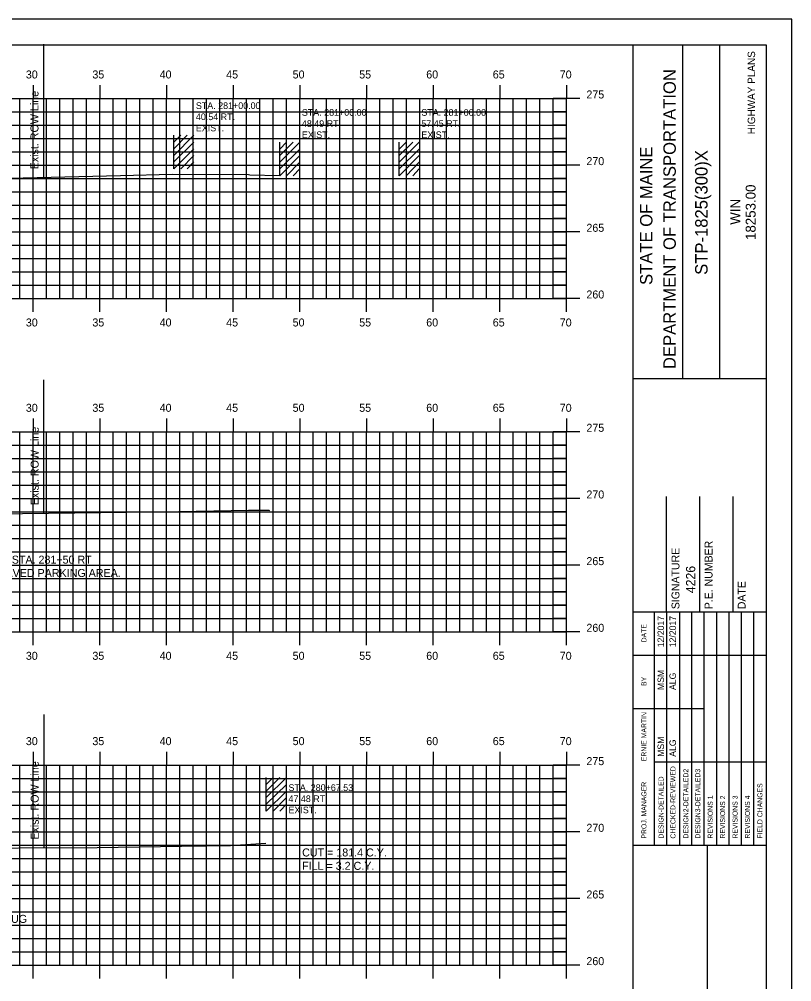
# Model space of a CAD drawing. Extents: x 855344 to 855514, y 366268 to 366378.
# Drawn here: x 855456.1 to 855514, y 366306 to 366378.2 of the extents above; entities that cross this region are included whole.
import ezdxf

# ---------------------------------------------------------------- set-up
doc = ezdxf.new("R2010")
doc.units = 0
for name, color, linetype in [('ANNOTATION', 7, 'Continuous'), ('BORDER', 7, 'Continuous'), ('D_Text_Monospaced', 7, 'Continuous'), ('E_ROW_Line', 7, 'Continuous'), ('H_V ANNOTATION', 7, 'Continuous'), ('HIGHWAY_TITLE', 7, 'Continuous'), ('MAJOR', 7, 'Continuous'), ('MINOR', 7, 'Continuous'), ('PLOT BOUNDARY', 7, 'Continuous'), ('S_Buildings', 7, 'Continuous'), ('S_Buildings_Attachments', 7, 'Continuous'), ('S_Buildings_SillElevation', 7, 'Continuous'), ('S_Roadway_Centerline', 7, 'Continuous')]:
    doc.layers.add(name, color=color, linetype=linetype)

msp = doc.modelspace()

# ---------------------------------------------------------------- linework, layer by layer
at = {"layer": 'BORDER'}
for p, q in [((855512.11, 366376.236), (855352.11, 366376.236)), ((855502.11, 366271.236), (855502.11, 366376.239)), ((855505.838, 366351.234), (855505.838, 366376.234)), ((855508.633, 366351.234), (855508.633, 366376.234)), ((855512.11, 366271.236), (855512.11, 366376.236)), ((855502.111, 366351.231), (855512.11, 366351.231)), ((855504.61, 366333.739), (855504.61, 366342.387)), ((855507.11, 366333.739), (855507.11, 366342.387)), ((855509.61, 366333.739), (855509.61, 366342.387)), ((855502.11, 366333.739), (855512.11, 366333.739)), ((855502.11, 366316.239), (855512.11, 366316.239)), ((855507.701, 366281.239), (855507.701, 366316.239))]:
    msp.add_line(p, q, dxfattribs=at)
for points in [[(855503.725, 366330.489), (855503.725, 366333.739)], [(855504.657, 366316.242), (855504.657, 366333.739)], [(855505.589, 366333.739), (855505.589, 366316.242)], [(855506.521, 366316.242), (855506.521, 366333.739)], [(855507.452, 366316.242), (855507.452, 366333.739)], [(855508.384, 366316.242), (855508.384, 366333.739)], [(855509.316, 366316.242), (855509.316, 366333.739)], [(855510.247, 366316.242), (855510.247, 366333.739)], [(855511.179, 366316.242), (855511.179, 366333.739)], [(855503.726, 366316.242), (855503.726, 366333.033)], [(855502.11, 366330.489), (855512.11, 366330.489)], [(855502.11, 366326.489), (855503.726, 366326.489)], [(855503.725, 366326.489), (855507.451, 366326.489)], [(855503.725, 366322.489), (855512.11, 366322.489)]]:
    msp.add_lwpolyline(points, dxfattribs=at)
at = {"layer": 'E_ROW_Line'}
for p, q in [((855457.905, 366366.321), (855457.905, 366376.321)), ((855457.92, 366341.126), (855457.92, 366351.126)), ((855457.925, 366316.044), (855457.925, 366326.044))]:
    msp.add_line(p, q, dxfattribs=at)
at = {"layer": 'MAJOR'}
for p, q in [((855457.11, 366373.238), (855457.11, 366372.236)), ((855462.11, 366373.238), (855462.11, 366372.236)), ((855467.11, 366373.238), (855467.11, 366372.236)), ((855472.11, 366373.238), (855472.11, 366372.236)), ((855477.11, 366373.238), (855477.11, 366372.236)), ((855482.11, 366373.238), (855482.11, 366372.236)), ((855487.11, 366373.238), (855487.11, 366372.236)), ((855492.11, 366373.238), (855492.11, 366372.236)), ((855497.11, 366373.238), (855497.11, 366372.236)), ((855357.11, 366372.236), (855497.11, 366372.236)), ((855357.11, 366372.236), (855497.11, 366372.236)), ((855457.11, 366357.236), (855457.11, 366372.236)), ((855462.11, 366357.236), (855462.11, 366372.236)), ((855467.11, 366357.236), (855467.11, 366372.236)), ((855472.11, 366357.236), (855472.11, 366372.236)), ((855477.11, 366357.236), (855477.11, 366372.236)), ((855482.11, 366357.236), (855482.11, 366372.236)), ((855487.11, 366357.236), (855487.11, 366372.236)), ((855492.11, 366357.236), (855492.11, 366372.236)), ((855498.112, 366372.236), (855496.108, 366372.236)), ((855497.11, 366357.236), (855497.11, 366372.236)), ((855497.11, 366357.236), (855497.11, 366372.236)), ((855357.11, 366367.236), (855497.11, 366367.236)), ((855498.112, 366367.236), (855496.108, 366367.236)), ((855357.11, 366362.236), (855497.11, 366362.236)), ((855498.112, 366362.236), (855496.108, 366362.236)), ((855357.11, 366357.236), (855497.11, 366357.236)), ((855357.11, 366357.236), (855497.11, 366357.236)), ((855457.11, 366356.234), (855457.11, 366357.236)), ((855462.11, 366356.234), (855462.11, 366357.236)), ((855467.11, 366356.234), (855467.11, 366357.236)), ((855472.11, 366356.234), (855472.11, 366357.236)), ((855477.11, 366356.234), (855477.11, 366357.236)), ((855482.11, 366356.234), (855482.11, 366357.236)), ((855487.11, 366356.234), (855487.11, 366357.236)), ((855492.11, 366356.234), (855492.11, 366357.236)), ((855498.112, 366357.236), (855496.108, 366357.236)), ((855497.11, 366356.234), (855497.11, 366357.236)), ((855457.11, 366348.238), (855457.11, 366347.236)), ((855462.11, 366348.238), (855462.11, 366347.236)), ((855467.11, 366348.238), (855467.11, 366347.236)), ((855472.11, 366348.238), (855472.11, 366347.236)), ((855477.11, 366348.238), (855477.11, 366347.236)), ((855482.11, 366348.238), (855482.11, 366347.236)), ((855487.11, 366348.238), (855487.11, 366347.236)), ((855492.11, 366348.238), (855492.11, 366347.236)), ((855497.11, 366348.238), (855497.11, 366347.236)), ((855357.11, 366347.236), (855497.11, 366347.236)), ((855357.11, 366347.236), (855497.11, 366347.236)), ((855457.11, 366332.236), (855457.11, 366347.236)), ((855462.11, 366332.236), (855462.11, 366347.236)), ((855467.11, 366332.236), (855467.11, 366347.236)), ((855472.11, 366332.236), (855472.11, 366347.236)), ((855477.11, 366332.236), (855477.11, 366347.236)), ((855482.11, 366332.236), (855482.11, 366347.236)), ((855487.11, 366332.236), (855487.11, 366347.236)), ((855492.11, 366332.236), (855492.11, 366347.236)), ((855498.112, 366347.236), (855496.108, 366347.236)), ((855497.11, 366332.236), (855497.11, 366347.236)), ((855497.11, 366332.236), (855497.11, 366347.236)), ((855357.11, 366342.236), (855497.11, 366342.236)), ((855498.112, 366342.236), (855496.108, 366342.236)), ((855357.11, 366337.236), (855497.11, 366337.236)), ((855498.112, 366337.236), (855496.108, 366337.236)), ((855357.11, 366332.236), (855497.11, 366332.236)), ((855357.11, 366332.236), (855497.11, 366332.236)), ((855457.11, 366331.234), (855457.11, 366332.236)), ((855462.11, 366331.234), (855462.11, 366332.236)), ((855467.11, 366331.234), (855467.11, 366332.236)), ((855472.11, 366331.234), (855472.11, 366332.236)), ((855477.11, 366331.234), (855477.11, 366332.236)), ((855482.11, 366331.234), (855482.11, 366332.236)), ((855487.11, 366331.234), (855487.11, 366332.236)), ((855492.11, 366331.234), (855492.11, 366332.236)), ((855498.112, 366332.236), (855496.108, 366332.236)), ((855497.11, 366331.234), (855497.11, 366332.236)), ((855457.11, 366323.238), (855457.11, 366322.236)), ((855462.11, 366323.238), (855462.11, 366322.236)), ((855467.11, 366323.238), (855467.11, 366322.236)), ((855472.11, 366323.238), (855472.11, 366322.236)), ((855477.11, 366323.238), (855477.11, 366322.236)), ((855482.11, 366323.238), (855482.11, 366322.236)), ((855487.11, 366323.238), (855487.11, 366322.236)), ((855492.11, 366323.238), (855492.11, 366322.236)), ((855497.11, 366323.238), (855497.11, 366322.236)), ((855357.11, 366322.236), (855497.11, 366322.236)), ((855357.11, 366322.236), (855497.11, 366322.236)), ((855457.11, 366307.236), (855457.11, 366322.236)), ((855462.11, 366307.236), (855462.11, 366322.236)), ((855467.11, 366307.236), (855467.11, 366322.236)), ((855472.11, 366307.236), (855472.11, 366322.236)), ((855477.11, 366307.236), (855477.11, 366322.236)), ((855482.11, 366307.236), (855482.11, 366322.236)), ((855487.11, 366307.236), (855487.11, 366322.236)), ((855492.11, 366307.236), (855492.11, 366322.236)), ((855498.112, 366322.236), (855496.108, 366322.236)), ((855497.11, 366307.236), (855497.11, 366322.236)), ((855497.11, 366307.236), (855497.11, 366322.236)), ((855357.11, 366317.236), (855497.11, 366317.236)), ((855498.112, 366317.236), (855496.108, 366317.236)), ((855357.11, 366312.236), (855497.11, 366312.236)), ((855498.112, 366312.236), (855496.108, 366312.236)), ((855357.11, 366307.236), (855497.11, 366307.236)), ((855357.11, 366307.236), (855497.11, 366307.236)), ((855457.11, 366306.234), (855457.11, 366307.236)), ((855462.11, 366306.234), (855462.11, 366307.236)), ((855467.11, 366306.234), (855467.11, 366307.236)), ((855472.11, 366306.234), (855472.11, 366307.236)), ((855477.11, 366306.234), (855477.11, 366307.236)), ((855482.11, 366306.234), (855482.11, 366307.236)), ((855487.11, 366306.234), (855487.11, 366307.236)), ((855492.11, 366306.234), (855492.11, 366307.236)), ((855498.112, 366307.236), (855496.108, 366307.236)), ((855497.11, 366306.234), (855497.11, 366307.236))]:
    msp.add_line(p, q, dxfattribs=at)
at = {"layer": 'MINOR'}
for p, q in [((855456.11, 366357.236), (855456.11, 366372.236)), ((855458.11, 366357.236), (855458.11, 366372.236)), ((855459.11, 366357.236), (855459.11, 366372.236)), ((855460.11, 366357.236), (855460.11, 366372.236)), ((855461.11, 366357.236), (855461.11, 366372.236)), ((855463.11, 366357.236), (855463.11, 366372.236)), ((855464.11, 366357.236), (855464.11, 366372.236)), ((855465.11, 366357.236), (855465.11, 366372.236)), ((855466.11, 366357.236), (855466.11, 366372.236)), ((855468.11, 366357.236), (855468.11, 366372.236)), ((855469.11, 366357.236), (855469.11, 366372.236)), ((855470.11, 366357.236), (855470.11, 366372.236)), ((855471.11, 366357.236), (855471.11, 366372.236)), ((855473.11, 366357.236), (855473.11, 366372.236)), ((855474.11, 366357.236), (855474.11, 366372.236)), ((855475.11, 366357.236), (855475.11, 366372.236)), ((855476.11, 366357.236), (855476.11, 366372.236)), ((855478.11, 366357.236), (855478.11, 366372.236)), ((855479.11, 366357.236), (855479.11, 366372.236)), ((855480.11, 366357.236), (855480.11, 366372.236)), ((855481.11, 366357.236), (855481.11, 366372.236)), ((855483.11, 366357.236), (855483.11, 366372.236)), ((855484.11, 366357.236), (855484.11, 366372.236)), ((855485.11, 366357.236), (855485.11, 366372.236)), ((855486.11, 366357.236), (855486.11, 366372.236)), ((855488.11, 366357.236), (855488.11, 366372.236)), ((855489.11, 366357.236), (855489.11, 366372.236)), ((855490.11, 366357.236), (855490.11, 366372.236)), ((855491.11, 366357.236), (855491.11, 366372.236)), ((855493.11, 366357.236), (855493.11, 366372.236)), ((855494.11, 366357.236), (855494.11, 366372.236)), ((855495.11, 366357.236), (855495.11, 366372.236)), ((855496.11, 366357.236), (855496.11, 366372.236)), ((855357.11, 366371.236), (855497.11, 366371.236)), ((855497.11, 366371.236), (855496.108, 366371.236)), ((855357.11, 366370.236), (855497.11, 366370.236)), ((855497.11, 366370.236), (855496.108, 366370.236)), ((855357.11, 366369.236), (855497.11, 366369.236)), ((855497.11, 366369.236), (855496.108, 366369.236)), ((855357.11, 366368.236), (855497.11, 366368.236)), ((855497.11, 366368.236), (855496.108, 366368.236)), ((855357.11, 366366.236), (855497.11, 366366.236)), ((855497.11, 366366.236), (855496.108, 366366.236)), ((855357.11, 366365.236), (855497.11, 366365.236)), ((855497.11, 366365.236), (855496.108, 366365.236)), ((855357.11, 366364.236), (855497.11, 366364.236)), ((855497.11, 366364.236), (855496.108, 366364.236)), ((855357.11, 366363.236), (855497.11, 366363.236)), ((855497.11, 366363.236), (855496.108, 366363.236)), ((855357.11, 366361.236), (855497.11, 366361.236)), ((855497.11, 366361.236), (855496.108, 366361.236)), ((855357.11, 366360.236), (855497.11, 366360.236)), ((855497.11, 366360.236), (855496.108, 366360.236)), ((855357.11, 366359.236), (855497.11, 366359.236)), ((855497.11, 366359.236), (855496.108, 366359.236)), ((855357.11, 366358.236), (855497.11, 366358.236)), ((855497.11, 366358.236), (855496.108, 366358.236)), ((855456.11, 366332.236), (855456.11, 366347.236)), ((855458.11, 366332.236), (855458.11, 366347.236)), ((855459.11, 366332.236), (855459.11, 366347.236)), ((855460.11, 366332.236), (855460.11, 366347.236)), ((855461.11, 366332.236), (855461.11, 366347.236)), ((855463.11, 366332.236), (855463.11, 366347.236)), ((855464.11, 366332.236), (855464.11, 366347.236)), ((855465.11, 366332.236), (855465.11, 366347.236)), ((855466.11, 366332.236), (855466.11, 366347.236)), ((855468.11, 366332.236), (855468.11, 366347.236)), ((855469.11, 366332.236), (855469.11, 366347.236)), ((855470.11, 366332.236), (855470.11, 366347.236)), ((855471.11, 366332.236), (855471.11, 366347.236)), ((855473.11, 366332.236), (855473.11, 366347.236)), ((855474.11, 366332.236), (855474.11, 366347.236)), ((855475.11, 366332.236), (855475.11, 366347.236)), ((855476.11, 366332.236), (855476.11, 366347.236)), ((855478.11, 366332.236), (855478.11, 366347.236)), ((855479.11, 366332.236), (855479.11, 366347.236)), ((855480.11, 366332.236), (855480.11, 366347.236)), ((855481.11, 366332.236), (855481.11, 366347.236)), ((855483.11, 366332.236), (855483.11, 366347.236)), ((855484.11, 366332.236), (855484.11, 366347.236)), ((855485.11, 366332.236), (855485.11, 366347.236)), ((855486.11, 366332.236), (855486.11, 366347.236)), ((855488.11, 366332.236), (855488.11, 366347.236)), ((855489.11, 366332.236), (855489.11, 366347.236)), ((855490.11, 366332.236), (855490.11, 366347.236)), ((855491.11, 366332.236), (855491.11, 366347.236)), ((855493.11, 366332.236), (855493.11, 366347.236)), ((855494.11, 366332.236), (855494.11, 366347.236)), ((855495.11, 366332.236), (855495.11, 366347.236)), ((855496.11, 366332.236), (855496.11, 366347.236)), ((855357.11, 366346.236), (855497.11, 366346.236)), ((855497.11, 366346.236), (855496.108, 366346.236)), ((855357.11, 366345.236), (855497.11, 366345.236)), ((855497.11, 366345.236), (855496.108, 366345.236)), ((855357.11, 366344.236), (855497.11, 366344.236)), ((855497.11, 366344.236), (855496.108, 366344.236)), ((855357.11, 366343.236), (855497.11, 366343.236)), ((855497.11, 366343.236), (855496.108, 366343.236)), ((855357.11, 366341.236), (855497.11, 366341.236)), ((855497.11, 366341.236), (855496.108, 366341.236)), ((855357.11, 366340.236), (855497.11, 366340.236)), ((855497.11, 366340.236), (855496.108, 366340.236)), ((855357.11, 366339.236), (855497.11, 366339.236)), ((855497.11, 366339.236), (855496.108, 366339.236)), ((855357.11, 366338.236), (855497.11, 366338.236)), ((855497.11, 366338.236), (855496.108, 366338.236)), ((855357.11, 366336.236), (855497.11, 366336.236)), ((855497.11, 366336.236), (855496.108, 366336.236)), ((855357.11, 366335.236), (855497.11, 366335.236)), ((855497.11, 366335.236), (855496.108, 366335.236)), ((855357.11, 366334.236), (855497.11, 366334.236)), ((855497.11, 366334.236), (855496.108, 366334.236)), ((855357.11, 366333.236), (855497.11, 366333.236)), ((855497.11, 366333.236), (855496.108, 366333.236)), ((855456.11, 366307.236), (855456.11, 366322.236)), ((855458.11, 366307.236), (855458.11, 366322.236)), ((855459.11, 366307.236), (855459.11, 366322.236)), ((855460.11, 366307.236), (855460.11, 366322.236)), ((855461.11, 366307.236), (855461.11, 366322.236)), ((855463.11, 366307.236), (855463.11, 366322.236)), ((855464.11, 366307.236), (855464.11, 366322.236)), ((855465.11, 366307.236), (855465.11, 366322.236)), ((855466.11, 366307.236), (855466.11, 366322.236)), ((855468.11, 366307.236), (855468.11, 366322.236)), ((855469.11, 366307.236), (855469.11, 366322.236)), ((855470.11, 366307.236), (855470.11, 366322.236)), ((855471.11, 366307.236), (855471.11, 366322.236)), ((855473.11, 366307.236), (855473.11, 366322.236)), ((855474.11, 366307.236), (855474.11, 366322.236)), ((855475.11, 366307.236), (855475.11, 366322.236)), ((855476.11, 366307.236), (855476.11, 366322.236)), ((855478.11, 366307.236), (855478.11, 366322.236)), ((855479.11, 366307.236), (855479.11, 366322.236)), ((855480.11, 366307.236), (855480.11, 366322.236)), ((855481.11, 366307.236), (855481.11, 366322.236)), ((855483.11, 366307.236), (855483.11, 366322.236)), ((855484.11, 366307.236), (855484.11, 366322.236)), ((855485.11, 366307.236), (855485.11, 366322.236)), ((855486.11, 366307.236), (855486.11, 366322.236)), ((855488.11, 366307.236), (855488.11, 366322.236)), ((855489.11, 366307.236), (855489.11, 366322.236)), ((855490.11, 366307.236), (855490.11, 366322.236)), ((855491.11, 366307.236), (855491.11, 366322.236)), ((855493.11, 366307.236), (855493.11, 366322.236)), ((855494.11, 366307.236), (855494.11, 366322.236)), ((855495.11, 366307.236), (855495.11, 366322.236)), ((855496.11, 366307.236), (855496.11, 366322.236)), ((855357.11, 366321.236), (855497.11, 366321.236)), ((855497.11, 366321.236), (855496.108, 366321.236)), ((855357.11, 366320.236), (855497.11, 366320.236)), ((855497.11, 366320.236), (855496.108, 366320.236)), ((855357.11, 366319.236), (855497.11, 366319.236)), ((855497.11, 366319.236), (855496.108, 366319.236)), ((855357.11, 366318.236), (855497.11, 366318.236)), ((855497.11, 366318.236), (855496.108, 366318.236)), ((855357.11, 366316.236), (855497.11, 366316.236)), ((855497.11, 366316.236), (855496.108, 366316.236)), ((855357.11, 366315.236), (855497.11, 366315.236)), ((855497.11, 366315.236), (855496.108, 366315.236)), ((855357.11, 366314.236), (855497.11, 366314.236)), ((855497.11, 366314.236), (855496.108, 366314.236)), ((855357.11, 366313.236), (855497.11, 366313.236)), ((855497.11, 366313.236), (855496.108, 366313.236)), ((855357.11, 366311.236), (855497.11, 366311.236)), ((855497.11, 366311.236), (855496.108, 366311.236)), ((855357.11, 366310.236), (855497.11, 366310.236)), ((855497.11, 366310.236), (855496.108, 366310.236)), ((855357.11, 366309.236), (855497.11, 366309.236)), ((855497.11, 366309.236), (855496.108, 366309.236)), ((855357.11, 366308.236), (855497.11, 366308.236)), ((855497.11, 366308.236), (855496.108, 366308.236))]:
    msp.add_line(p, q, dxfattribs=at)
at = {"layer": 'PLOT BOUNDARY'}
msp.add_lwpolyline([(855344.016, 366268.177), (855514.016, 366268.177), (855514.016, 366378.177), (855344.016, 366378.177)], close=True, dxfattribs=at)
at = {"layer": 'S_Buildings'}
for p, q in [((855475.6, 366366.439), (855475.6, 366368.965)), ((855475.6, 366367.456), (855477.109, 366368.965)), ((855475.6, 366367.948), (855476.617, 366368.965)), ((855475.6, 366368.44), (855476.125, 366368.965)), ((855475.6, 366366.964), (855477.109, 366368.44)), ((855484.562, 366366.439), (855484.562, 366368.965)), ((855484.562, 366367.456), (855486.071, 366368.965)), ((855484.562, 366367.948), (855485.579, 366368.965)), ((855484.562, 366368.44), (855485.087, 366368.965)), ((855484.562, 366366.964), (855486.071, 366368.44)), ((855475.6, 366366.439), (855477.109, 366367.948)), ((855484.562, 366366.439), (855486.071, 366367.948)), ((855476.125, 366366.439), (855477.109, 366367.456)), ((855476.617, 366366.439), (855477.109, 366366.964)), ((855485.087, 366366.439), (855486.071, 366367.456)), ((855485.579, 366366.439), (855486.071, 366366.964))]:
    msp.add_line(p, q, dxfattribs=at)
at = {"layer": 'S_Buildings_Attachments'}
for p, q in [((855467.649, 366366.949), (855467.649, 366369.475)), ((855467.649, 366367.966), (855469.158, 366369.475)), ((855467.649, 366368.458), (855468.666, 366369.475)), ((855467.649, 366368.95), (855468.174, 366369.475)), ((855467.649, 366367.474), (855469.158, 366368.95)), ((855467.649, 366366.949), (855469.158, 366368.458)), ((855468.174, 366366.949), (855469.158, 366367.966)), ((855468.666, 366366.949), (855469.158, 366367.474))]:
    msp.add_line(p, q, dxfattribs=at)
at = {"layer": 'S_Buildings_SillElevation'}
for p, q in [((855474.593, 366318.784), (855474.593, 366321.311)), ((855474.593, 366319.801), (855476.102, 366321.311)), ((855474.593, 366320.293), (855475.61, 366321.311)), ((855474.593, 366320.786), (855475.118, 366321.311)), ((855474.593, 366319.309), (855476.102, 366320.786)), ((855474.593, 366318.784), (855476.102, 366320.293)), ((855475.118, 366318.784), (855476.102, 366319.801)), ((855475.61, 366318.784), (855476.102, 366319.309))]:
    msp.add_line(p, q, dxfattribs=at)
at = {"layer": 'S_Roadway_Centerline'}
for points in [[(855450.069, 366366.134), (855463.667, 366366.46), (855467.523, 366366.551), (855473.251, 366366.54), (855473.364, 366366.499), (855475.585, 366366.447), (855475.6, 366366.439)], [(855384.275, 366339.699), (855388.432, 366339.882), (855400.711, 366340.39), (855405.927, 366340.564), (855407.101, 366340.624), (855408.927, 366340.586), (855411.541, 366340.585), (855413.757, 366340.668), (855416.384, 366340.7), (855420.216, 366340.964), (855427.216, 366341.257), (855437.021, 366341.068), (855437.99, 366341.069), (855438.987, 366341.077), (855442.502, 366341.148), (855443.985, 366340.92), (855449.999, 366341.018), (855450.133, 366341.025), (855450.439, 366341.026), (855468.024, 366341.26), (855473.254, 366341.359), (855474.777, 366341.358), (855474.83, 366341.346)], [(855381.561, 366314.634), (855381.949, 366314.641), (855385.679, 366314.793), (855405.358, 366315.606), (855406.311, 366315.638), (855406.526, 366315.649), (855406.86, 366315.642), (855411.326, 366315.64), (855415.114, 366315.783), (855416.377, 366315.798), (855418.219, 366315.925), (855427.262, 366316.303), (855433.603, 366316.181), (855438.043, 366316.107), (855438.522, 366316.091), (855442.641, 366316.173), (855445.301, 366315.765), (855445.453, 366315.764), (855450.115, 366316.007), (855461.901, 366316.064), (855468.238, 366316.148), (855471.911, 366316.218), (855474.551, 366316.376)]]:
    msp.add_lwpolyline(points, dxfattribs=at)

# ---------------------------------------------------------------- texts
at = {"layer": 'ANNOTATION'}
for s, p in [('STA. 280+22 TO STA. 281+50 RT', (855449.237, 366337.348)), ('CONSTRUCT PAVED PARKING AREA.', (855449.237, 366336.348)), ('CUT = 181.4 C.Y.', (855477.286, 366315.386)), ('FILL = 3.2 C.Y.', (855477.286, 366314.384)), ('REMOVE AND PLUG', (855448.85, 366310.404))]:
    msp.add_text(s, height=0.6, dxfattribs=at).set_placement(p)
msp.add_text('4226', height=0.69, rotation=90, dxfattribs=at).set_placement((855506.774, 366335.13))
at = {"layer": 'BORDER'}
for s, height, p in [('DEPARTMENT OF TRANSPORTATION', 0.93176, (855505.317, 366351.942)), ('STATE OF MAINE', 0.93176, (855503.565, 366358.248)), ('STP-1825(300)X', 0.93176, (855507.702, 366359.008)), ('18253.00', 0.7453, (855511.305, 366361.623)), ('WIN', 0.7453, (855510.147, 366362.766)), ('P.E. NUMBER', 0.59055, (855508.071, 366333.932)), ('SIGNATURE', 0.5906, (855505.59, 366333.932)), ('DATE', 0.5906, (855510.551, 366333.932)), ('12/2017', 0.4845, (855504.433, 366331.081)), ('12/2017', 0.4845, (855505.327, 366331.081)), ('DATE', 0.3714, (855503.114, 366331.445)), ('MSM', 0.4845, (855504.433, 366327.872)), ('BY', 0.3714, (855503.114, 366328.174)), ('ALG', 0.4845, (855505.327, 366327.872)), ('ERNIE MARTIN', 0.37275, (855503.114, 366322.531)), ('MSM', 0.4845, (855504.433, 366322.863)), ('ALG', 0.4845, (855505.327, 366322.863)), ('CHECKED-REVIEWED', 0.37275, (855505.291, 366316.727)), ('DESIGN2-DETAILED2', 0.37275, (855506.26, 366316.727)), ('DESIGN3-DETAILED3', 0.37275, (855507.154, 366316.727)), ('PROJ. MANAGER', 0.37275, (855503.114, 366316.727)), ('DESIGN-DETAILED', 0.37275, (855504.396, 366316.727)), ('FIELD CHANGES', 0.37275, (855511.813, 366316.727)), ('REVISIONS 1', 0.37275, (855508.086, 366316.727)), ('REVISIONS 2', 0.37275, (855509.018, 366316.727)), ('REVISIONS 3', 0.37275, (855509.949, 366316.727)), ('REVISIONS 4', 0.37275, (855510.881, 366316.727))]:
    msp.add_text(s, height=height, rotation=90, dxfattribs=at).set_placement(p)
at = {"layer": 'D_Text_Monospaced'}
for s, height, p in [('STA. 281+00.00', 0.49998, (855469.316, 366371.447)), ('STA. 281+00.00', 0.49998, (855477.267, 366370.937)), ('STA. 281+00.00', 0.49998, (855486.229, 366370.937)), ('40.54 RT.', 0.5, (855469.316, 366370.613)), ('48.49 RT.', 0.5, (855477.267, 366370.103)), ('57.45 RT.', 0.5, (855486.229, 366370.103)), ('EXIST. ', 0.5, (855469.316, 366369.773)), ('EXIST. ', 0.5, (855477.267, 366369.263)), ('EXIST. ', 0.5, (855486.229, 366369.263)), ('STA. 280+67.53', 0.49998, (855476.26, 366320.299)), ('47.48 RT.', 0.5, (855476.26, 366319.465)), ('EXIST. ', 0.5, (855476.26, 366318.625))]:
    msp.add_text(s, height=height, dxfattribs=at).set_placement(p)
at = {"layer": 'E_ROW_Line'}
for p in [(855457.505, 366366.921), (855457.52, 366341.726), (855457.525, 366316.644)]:
    msp.add_text('Exist. ROW Line', height=0.6, rotation=90, dxfattribs=at).set_placement(p)
at = {"layer": 'H_V ANNOTATION'}
for s, p in [('30', (855456.558, 366373.736)), ('35', (855461.55, 366373.736)), ('40', (855466.596, 366373.736)), ('45', (855471.588, 366373.736)), ('50', (855476.574, 366373.736)), ('55', (855481.566, 366373.736)), ('60', (855486.596, 366373.736)), ('65', (855491.588, 366373.736)), ('70', (855496.612, 366373.736)), ('275', (855498.61, 366372.236)), ('270', (855498.61, 366367.236)), ('265', (855498.61, 366362.236)), ('260', (855498.61, 366357.236)), ('30', (855456.558, 366355.136)), ('35', (855461.55, 366355.136)), ('40', (855466.596, 366355.136)), ('45', (855471.588, 366355.136)), ('50', (855476.574, 366355.136)), ('55', (855481.566, 366355.136)), ('60', (855486.596, 366355.136)), ('65', (855491.588, 366355.136)), ('70', (855496.612, 366355.136)), ('30', (855456.558, 366348.736)), ('35', (855461.55, 366348.736)), ('40', (855466.596, 366348.736)), ('45', (855471.588, 366348.736)), ('50', (855476.574, 366348.736)), ('55', (855481.566, 366348.736)), ('60', (855486.596, 366348.736)), ('65', (855491.588, 366348.736)), ('70', (855496.612, 366348.736)), ('275', (855498.61, 366347.236)), ('270', (855498.61, 366342.236)), ('265', (855498.61, 366337.236)), ('260', (855498.61, 366332.236)), ('30', (855456.558, 366330.136)), ('35', (855461.55, 366330.136)), ('40', (855466.596, 366330.136)), ('45', (855471.588, 366330.136)), ('50', (855476.574, 366330.136)), ('55', (855481.566, 366330.136)), ('60', (855486.596, 366330.136)), ('65', (855491.588, 366330.136)), ('70', (855496.612, 366330.136)), ('30', (855456.558, 366323.736)), ('35', (855461.55, 366323.736)), ('40', (855466.596, 366323.736)), ('45', (855471.588, 366323.736)), ('50', (855476.574, 366323.736)), ('55', (855481.566, 366323.736)), ('60', (855486.596, 366323.736)), ('65', (855491.588, 366323.736)), ('70', (855496.612, 366323.736)), ('275', (855498.61, 366322.236)), ('270', (855498.61, 366317.236)), ('265', (855498.61, 366312.236)), ('260', (855498.61, 366307.236))]:
    msp.add_text(s, height=0.6, dxfattribs=at).set_placement(p)
at = {"layer": 'HIGHWAY_TITLE'}
msp.add_text('HIGHWAY PLANS', height=0.55901, rotation=90, dxfattribs=at).set_placement((855511.268, 366369.552))

doc.saveas('drawing.dxf')
